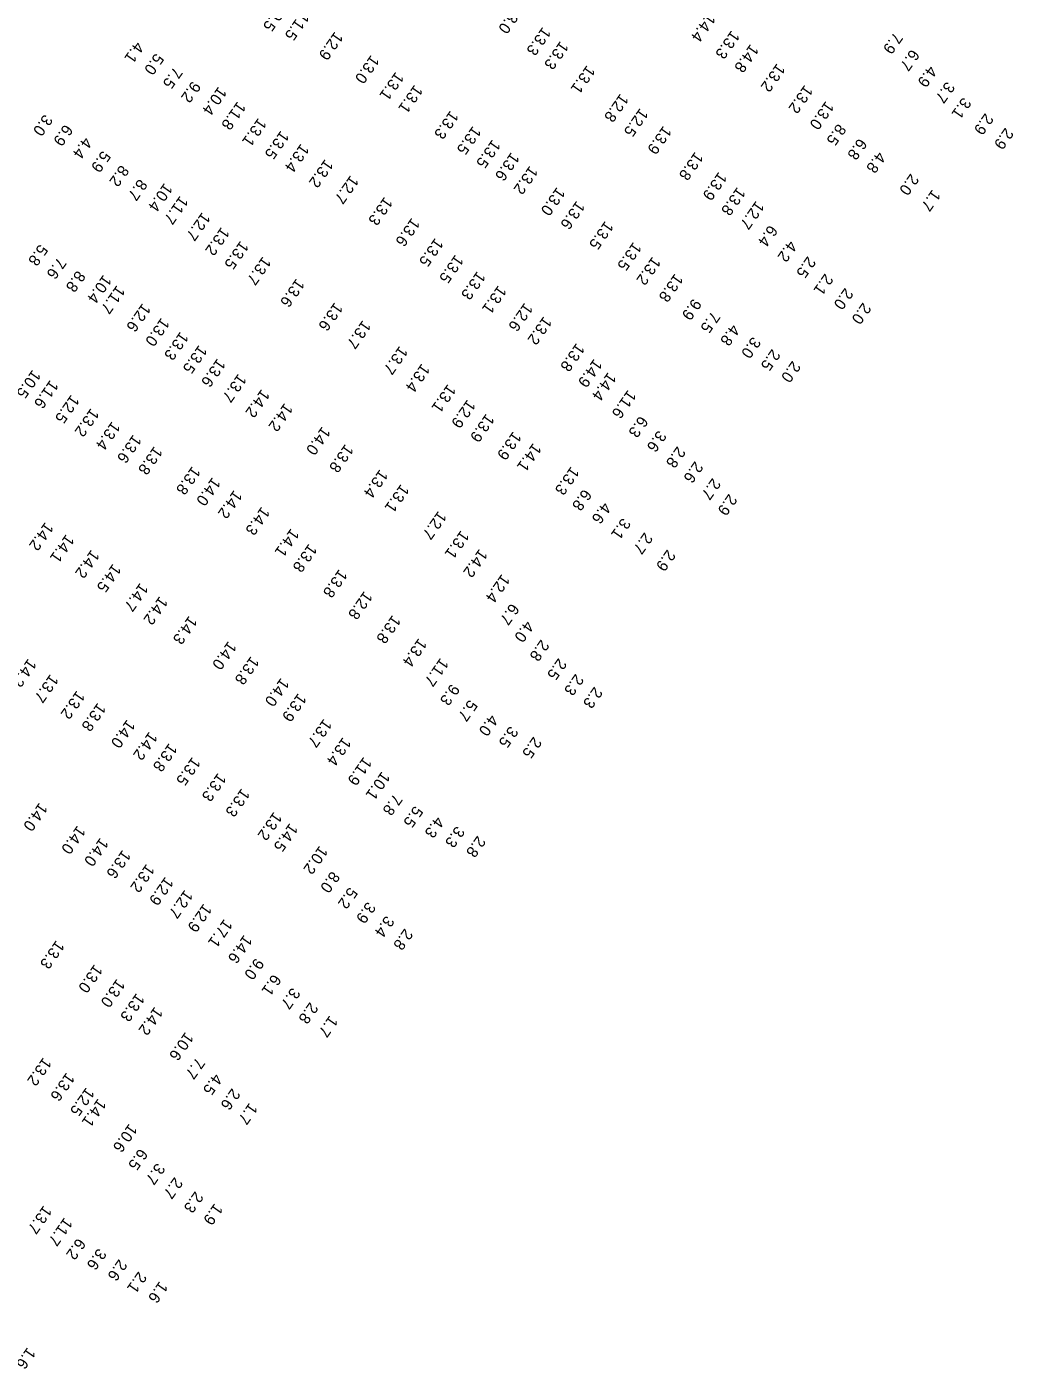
# Model space of a CAD drawing. Extents: x 815385 to 820851, y 582449 to 604245.
# Drawn here: x 819579 to 820016, y 588067 to 588662 of the extents above; entities that cross this region are included whole.
import ezdxf

# ---------------------------------------------------------------- set-up
doc = ezdxf.new("R2010")
doc.units = 0
doc.layers.add('V-TOPO-SOUN-021309', color=7, linetype='Continuous')
doc.layers.add('V-TOPO-SOUN-021509', color=7, linetype='Continuous')

msp = doc.modelspace()

# ---------------------------------------------------------------- texts
at = {"layer": 'V-TOPO-SOUN-021309'}
for s, p in [('9.5', (819688.75, 588669.65)), ('11.5 ', (819700.55, 588668.68)), ('13.0 ', (819795.22, 588671.68)), ('14.4 ', (819880.66, 588668.03)), ('12.9 ', (819715.58, 588659.95)), ('13.3 ', (819807.72, 588662.01)), ('13.3 ', (819891.42, 588660.46)), ('4.1', (819627.33, 588655.57)), ('13.3 ', (819815.54, 588655.75)), ('14.8 ', (819899.84, 588654.42)), ('7.9', (819963.61, 588659.66)), ('5.0', (819636.09, 588650.38)), ('13.0 ', (819731.64, 588649.57)), ('6.7', (819971.08, 588652.14)), ('7.5', (819644.32, 588644.28)), ('13.1 ', (819742.54, 588642.1)), ('13.1 ', (819827.32, 588645.03)), ('13.2 ', (819911.57, 588645.84)), ('4.9', (819978.92, 588644.91)), ('9.2', (819652.41, 588638.04)), ('13.1 ', (819750.9, 588636.38)), ('13.2 ', (819923.86, 588636.32)), ('3.7', (819986.74, 588637.84)), ('10.4 ', (819664, 588635.57)), ('12.8 ', (819842.14, 588632.46)), ('3.1', (819994.02, 588630.84)), ('11.8 ', (819672.44, 588628.99)), ('13.3 ', (819766.79, 588624.92)), ('12.5 ', (819850.85, 588626)), ('13.0 ', (819933.22, 588629.15)), ('3.0', (819586.8, 588623.29)), ('6.9', (819595.78, 588618.86)), ('13.1 ', (819681.65, 588621.67)), ('13.9 ', (819861.25, 588618.21)), ('8.5', (819938.55, 588619.11)), ('2.9', (820003.91, 588623.79)), ('4.4', (819604.38, 588613.25)), ('13.5 ', (819691.63, 588616.05)), ('13.5 ', (819776.77, 588618.09)), ('2.9', (820012.81, 588617.34)), ('5.9', (819612.51, 588607.17)), ('13.4 ', (819700.53, 588610.26)), ('13.5 ', (819785.39, 588612.09)), ('13.6 ', (819793.76, 588606.42)), ('13.8 ', (819875.28, 588606.66)), ('6.8', (819947.83, 588612.68)), ('4.8', (819956.2, 588606.83)), ('8.2', (819620.64, 588600.84)), ('13.2 ', (819711.24, 588603.41)), ('13.2 ', (819801.98, 588600.45)), ('8.7', (819628.77, 588594.65)), ('12.7 ', (819722.51, 588596.24)), ('13.9 ', (819885.77, 588597.76)), ('2.0', (819970.83, 588597.02)), ('10.4 ', (819640.02, 588592.83)), ('13.0 ', (819814.03, 588591)), ('13.8 ', (819894, 588591.03)), ('1.7', (819980.46, 588589.94)), ('11.7 ', (819646.95, 588587.17)), ('13.3 ', (819737.57, 588586.7)), ('13.6 ', (819822.77, 588584.94)), ('12.7 ', (819902.31, 588584.93)), ('12.7 ', (819656.75, 588579.89)), ('13.6 ', (819749.66, 588577.39)), ('13.2 ', (819665.27, 588573.3)), ('13.5 ', (819835.44, 588576.02)), ('6.4', (819908.2, 588574.25)), ('5.8', (819584.67, 588565.72)), ('13.5 ', (819673.74, 588567.2)), ('13.5 ', (819760.05, 588568.45)), ('13.5 ', (819847.93, 588566.67)), ('4.2', (819916.89, 588567.43)), ('7.6', (819592.83, 588559.89)), ('13.7 ', (819683.65, 588560.27)), ('13.5 ', (819769, 588561.08)), ('13.2 ', (819856.41, 588560.22)), ('2.5', (819925.15, 588560.34)), ('8.8', (819601.32, 588554.06)), ('13.3 ', (819778.72, 588553.74)), ('13.8 ', (819866.34, 588552.71)), ('2.1', (819932.86, 588552.7)), ('10.4 ', (819612.99, 588552.19)), ('11.7 ', (819618.93, 588547.51)), ('13.6 ', (819698.53, 588550.48)), ('13.1 ', (819788.03, 588547.46)), ('9.9', (819874.4, 588541.65)), ('2.0', (819941.75, 588546.35)), ('12.6 ', (819630.31, 588539.53)), ('13.6 ', (819715.48, 588539.91)), ('12.6 ', (819799.7, 588539.74)), ('7.5', (819882.68, 588535.97)), ('2.0', (819949.68, 588539.85)), ('13.0 ', (819638.67, 588533.11)), ('13.7 ', (819727.93, 588532.01)), ('13.2 ', (819808.17, 588533.74)), ('4.8', (819891.47, 588530.27)), ('13.3 ', (819647.07, 588526.93)), ('3.0', (819900.74, 588524.73)), ('13.5 ', (819655.31, 588521.03)), ('13.7 ', (819744.26, 588520.59)), ('13.8 ', (819822.7, 588521.89)), ('2.5', (819909.41, 588519.25)), ('13.6 ', (819663.5, 588515.05)), ('13.4 ', (819754.09, 588512.79)), ('14.9 ', (819830.49, 588514.91)), ('2.0', (819918.43, 588514.02)), ('10.5 ', (819581.56, 588510.07)), ('11.6 ', (819589.39, 588505.55)), ('13.7 ', (819672.78, 588508.29)), ('14.4 ', (819836.72, 588508.98)), ('14.2 ', (819683.07, 588501.47)), ('13.1 ', (819765.64, 588503.67)), ('11.6 ', (819845.54, 588501.15)), ('12.5 ', (819598.68, 588498.98)), ('14.2 ', (819693.31, 588495.33)), ('12.9 ', (819774.35, 588496.85)), ('13.2 ', (819607.41, 588493.01)), ('13.9 ', (819782.67, 588490.61)), ('6.3', (819850.78, 588489.63)), ('13.4 ', (819616.8, 588487.18)), ('13.6 ', (819626.21, 588481.34)), ('14.0 ', (819709.97, 588484.9)), ('13.9 ', (819794.64, 588482.72)), ('3.6', (819858.92, 588483.22)), ('13.8 ', (819635.52, 588476.16)), ('13.8 ', (819720.2, 588477.11)), ('14.1 ', (819803.5, 588477.56)), ('2.8', (819867.4, 588476.14)), ('2.6', (819875.19, 588469.49)), ('13.8 ', (819652.35, 588467.3)), ('13.4 ', (819735.5, 588465.89)), ('13.3 ', (819820.3, 588467.18)), ('14.0 ', (819661.29, 588462.4)), ('13.1 ', (819744.87, 588459.37)), ('2.7', (819883, 588462.06)), ('14.2 ', (819670.89, 588456.73)), ('6.8', (819825.78, 588457.19)), ('2.9', (819890.27, 588455.06)), ('14.3 ', (819683.1, 588449.36)), ('12.7 ', (819761.47, 588447.47)), ('4.6', (819834.47, 588451.42)), ('14.2 ', (819587.18, 588442.52)), ('14.1 ', (819696.12, 588439.72)), ('3.1', (819843.06, 588444.43)), ('14.1 ', (819596.45, 588437.14)), ('13.1 ', (819771.49, 588438.88)), ('2.7', (819852.84, 588437.94)), ('14.2 ', (819607.6, 588430.28)), ('13.8 ', (819704.05, 588432.93)), ('14.2 ', (819779.64, 588430.66)), ('2.9', (819862.96, 588430.39)), ('14.5 ', (819617.18, 588424.06)), ('13.8 ', (819717.48, 588421.67)), ('12.4 ', (819789.58, 588419.5)), ('14.7 ', (819629.23, 588415.58)), ('12.8 ', (819728.63, 588411.97)), ('14.2 ', (819637.88, 588409.65)), ('6.7', (819793.67, 588406.54)), ('14.3 ', (819650.94, 588400.99)), ('13.8 ', (819741.14, 588401.33)), ('4.0', (819800.17, 588398.89)), ('14.0 ', (819668.34, 588389.74)), ('13.4 ', (819752.76, 588391.05)), ('2.8', (819806.97, 588390.48)), ('13.8 ', (819678.36, 588383.09)), ('11.7 ', (819762.39, 588382.33)), ('2.5', (819814.71, 588382.21)), ('2.3', (819822.27, 588375.27)), ('14.0 ', (819691.68, 588373.47)), ('9.3', (819767.2, 588370.86)), ('2.3', (819830.62, 588369.58)), ('13.9 ', (819699.33, 588366.69)), ('5.7', (819775.14, 588363.84)), ('4.0', (819784.39, 588357.31)), ('13.7 ', (819710.66, 588355.33)), ('3.5', (819793.2, 588352.15)), ('13.4 ', (819719.14, 588347.19)), ('2.5', (819803.64, 588347.43)), ('11.9 ', (819728.35, 588338.47)), ('10.1 ', (819736.42, 588332)), ('7.8', (819741.8, 588322.1)), ('5.5', (819750.98, 588316.79)), ('4.3', (819760.42, 588312.13)), ('3.3', (819769.47, 588307.83)), ('2.8', (819778.79, 588303.52))]:
    msp.add_text(s, height=5, rotation=234.911, dxfattribs=at).set_placement(p)
at = {"layer": 'V-TOPO-SOUN-021509'}
for s, p in [('14.2 ', (819579.65, 588382.04)), ('13.7 ', (819589.41, 588375.12)), ('13.2 ', (819601.17, 588367.84)), ('13.8 ', (819610.45, 588362.43)), ('14.0 ', (819623.43, 588355.02)), ('14.2 ', (819633.3, 588349.66)), ('13.8 ', (819642.08, 588344.55)), ('13.5 ', (819652.38, 588338.43)), ('13.3 ', (819663.76, 588331.35)), ('13.3 ', (819674.23, 588324.51)), ('14.0 ', (819584.6, 588318.19)), ('13.2 ', (819688.53, 588314.09)), ('14.5 ', (819695.58, 588309.1)), ('14.0 ', (819601.44, 588308.01)), ('14.0 ', (819611.56, 588302.62)), ('13.6 ', (819621.47, 588297.24)), ('10.2 ', (819708.79, 588299.08)), ('13.2 ', (819632.05, 588291.01)), ('12.9 ', (819640.38, 588285.3)), ('8.0', (819714.12, 588287.82)), ('12.7 ', (819649.03, 588279.54)), ('5.2', (819721.98, 588280.74)), ('12.9 ', (819657.42, 588273.41)), ('3.9', (819730, 588274.26)), ('3.4', (819738.25, 588268.11)), ('17.1 ', (819666.52, 588266.6)), ('2.8', (819746.53, 588262.4)), ('13.3 ', (819592.04, 588257.14)), ('14.6 ', (819675.34, 588259.61)), ('13.0 ', (819609, 588246.53)), ('9.0', (819680.44, 588249.31)), ('13.0 ', (819618.93, 588240.07)), ('6.1', (819688.15, 588242.19)), ('13.3 ', (819627.63, 588233.76)), ('3.7', (819696.57, 588236.26)), ('14.2 ', (819635.7, 588227.71)), ('2.8', (819704.51, 588229.75)), ('1.7', (819713.28, 588223.83)), ('10.6 ', (819649.31, 588216.52)), ('13.2 ', (819586.35, 588205.28)), ('7.7', (819654.24, 588205.24)), ('13.6 ', (819596.61, 588198.55)), ('4.5', (819662.11, 588198.2)), ('12.5 ', (819605.35, 588191.95)), ('2.6', (819669.98, 588191.58)), ('14.1 ', (819610.59, 588187.03)), ('1.7', (819677.71, 588185.14)), ('10.6 ', (819624.35, 588175.87)), ('6.5', (819628.98, 588164.91)), ('3.7', (819636.63, 588158.47)), ('2.7', (819644.5, 588152.2)), ('2.3', (819653.64, 588145.92)), ('13.7 ', (819586.51, 588139.67)), ('1.9', (819662.27, 588140.58)), ('11.7 ', (819595.68, 588134.32)), ('6.2', (819601.47, 588125.19)), ('3.6', (819610.64, 588120.66)), ('2.6', (819619.86, 588115.82)), ('2.1', (819628.52, 588110.35)), ('1.6', (819637.86, 588106.01)), ('1.6', (819579.3, 588076.75))]:
    msp.add_text(s, height=5, rotation=234.911, dxfattribs=at).set_placement(p)

doc.saveas('drawing.dxf')
